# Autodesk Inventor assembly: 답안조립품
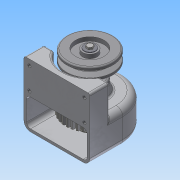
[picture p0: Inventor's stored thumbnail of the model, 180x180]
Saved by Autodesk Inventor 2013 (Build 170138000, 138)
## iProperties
Created: 2015-02
Part Number: 답안조립품
Document SubType Name: Assembly
Designer: Administrator
Author: Administrator
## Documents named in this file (14)
- C:\Documents and Settings\Administrator\바탕 화면\450214v1006\답안조립품.iam
- C:\Documents and Settings\Administrator\바탕 화면\450214v1006\1-본체.ipt
- C:\Documents and Settings\Administrator\바탕 화면\450214v1006\축.ipt
- C:\Documents and Settings\Administrator\바탕 화면\450214v1006\키5x5.ipt
- C:\Documents and Settings\Administrator\바탕 화면\450214v1006\베어링 6001.ipt
- C:\Documents and Settings\Administrator\바탕 화면\450214v1006\축커버.ipt
- C:\Documents and Settings\Administrator\바탕 화면\450214v1006\오일실.ipt
- C:\Documents and Settings\Administrator\바탕 화면\450214v1006\M3x0.5.ipt
- C:\Documents and Settings\Administrator\바탕 화면\450214v1006\4-V-벨트풀리.ipt
- C:\Documents and Settings\Administrator\바탕 화면\450214v1006\키4x4.ipt
- C:\Documents and Settings\Administrator\바탕 화면\450214v1006\M5x0.8.ipt
- M5x0.8.ipt
- C:\Documents and Settings\Administrator\바탕 화면\450214v1006\5-스퍼기어.ipt
- C:\Documents and Settings\Administrator\바탕 화면\450214v1006\와샤.ipt
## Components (7 placed, 4 different names)
1. 1-본체:1
2. 4-V-벨트풀리:1 — 플러쉬:1, 각도:2
3. M5x0.8:1 — 각도:3
4. M3x0.5:1
5. M3x0.5:2
6. M3x0.5:3
7. M3x0.5:4
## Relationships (3: Angle 2, Flush 1)
- 플러쉬:1 [Flush]: 4-V-벨트풀리:1
- 각도:2 [Angle]: 4-V-벨트풀리:1
- 각도:3 [Angle]: M5x0.8:1
